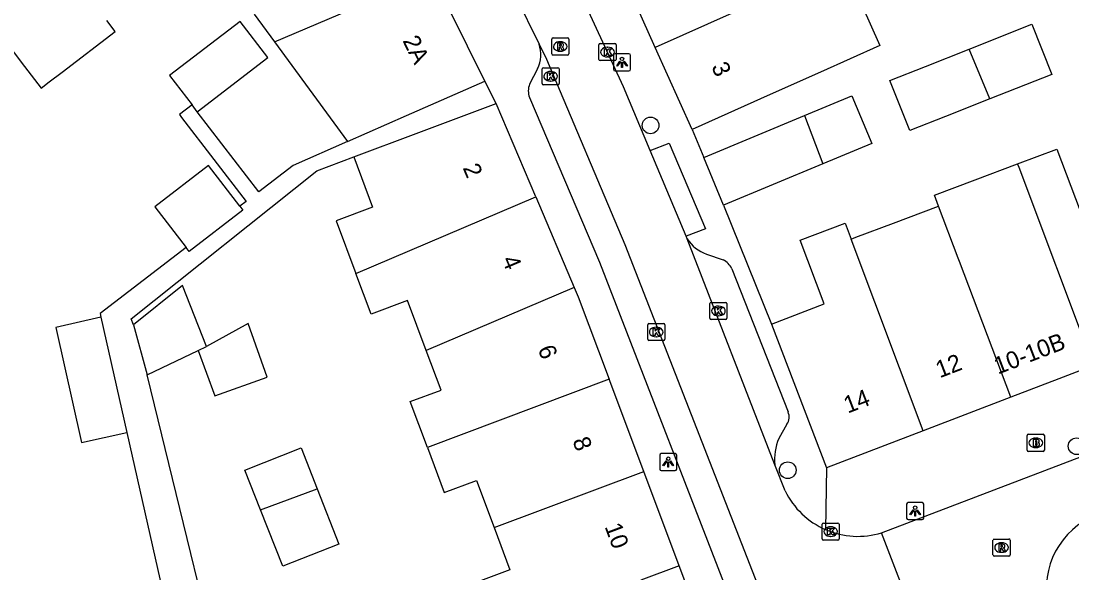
# Model space of a CAD drawing. Extents: x 159377 to 159983, y 382996 to 383595.
# Drawn here: x 159487.5 to 159549, y 383423.3 to 383455.6 of the extents above; entities that cross this region are included whole.
import ezdxf

# ---------------------------------------------------------------- set-up
doc = ezdxf.new("R2010")
doc.units = 0
for name, color, linetype in [('IMGEO_Boom', 7, 'Continuous'), ('IMGEO_Brandkraan', 7, 'Continuous'), ('IMGEO_Kolk', 7, 'Continuous'), ('IMGEO_Lichtpunt', 7, 'Continuous'), ('IMGEO_Muur', 7, 'Continuous'), ('IMGEO_Pand', 7, 'Continuous'), ('IMGEO_Pand_nummerreeks', 7, 'Continuous'), ('IMGEO_Rijbaan_lokaal_open', 7, 'Continuous'), ('IMGEO_Rioolput', 7, 'Continuous'), ('IMGEO_Voetpad_open', 7, 'Continuous')]:
    doc.layers.add(name, color=color, linetype=linetype)

msp = doc.modelspace()

# ---------------------------------------------------------------- linework, layer by layer
at = {"layer": 'IMGEO_Boom'}
for centre in [(159524.349, 383449.488), (159549.255, 383430.722), (159532.364, 383429.319)]:
    msp.add_circle(centre, 0.489, dxfattribs=at)
at = {"layer": 'IMGEO_Brandkraan'}
for p, q in [((159546.365, 383430.494), (159546.365, 383431.346)), ((159546.44, 383431.42), (159547.292, 383431.42)), ((159547.366, 383431.346), (159547.366, 383430.494)), ((159546.853, 383431.2), (159546.878, 383431.2)), ((159547.292, 383430.42), (159546.44, 383430.42)), ((159546.876, 383430.64), (159546.851, 383430.64))]:
    msp.add_line(p, q, dxfattribs=at)
for points in [[(159546.365, 383430.494), (159546.365, 383431.346)], [(159546.44, 383431.42), (159547.292, 383431.42)], [(159547.366, 383431.346), (159547.366, 383430.494)], [(159546.713, 383431.12), (159546.713, 383430.72), (159546.926, 383430.72)], [(159546.944, 383431.12), (159546.713, 383431.12)], [(159546.892, 383431.039), (159546.838, 383431.039), (159546.838, 383430.963)], [(159546.838, 383430.963), (159546.891, 383430.963)], [(159546.9, 383430.887), (159546.838, 383430.887), (159546.838, 383430.806)], [(159546.838, 383430.806), (159546.9, 383430.806)], [(159547.292, 383430.42), (159546.44, 383430.42)]]:
    msp.add_lwpolyline(points, dxfattribs=at)
for centre, radius, start, end in [((159546.442, 383431.344), 0.0765, 91.55205, 178.44795), ((159546.442, 383431.344), 0.0765, 91.55205, 178.44795), ((159547.29, 383431.344), 0.0765, 1.55205, 88.44795), ((159547.29, 383431.344), 0.0765, 1.55205, 88.44795), ((159546.893, 383431.001), 0.0379, 267.82845, 90.93552), ((159546.901, 383430.846), 0.0404, 269.87594, 90.50774), ((159546.932, 383430.971), 0.251, 268.66757, 293.53466), ((159546.948, 383430.975), 0.145, 59.4692, 91.53667), ((159546.973, 383431.022), 0.0922, 285.51372, 58.15012), ((159546.978, 383430.83), 0.105, 301.31148, 78.98903), ((159546.442, 383430.496), 0.0765, 181.55205, 268.44795), ((159546.442, 383430.496), 0.0765, 181.55205, 268.44795), ((159547.29, 383430.496), 0.0765, 271.55205, 358.44795), ((159547.29, 383430.496), 0.0765, 271.55205, 358.44795)]:
    msp.add_arc(centre, radius, start, end, dxfattribs=at)
for centre, major_axis, ratio, start_param, end_param in [((159546.852, 383430.92), (-0.387, 0.002), 0.722429, 4.712389, 7.853982), ((159546.877, 383430.92), (-0.39, 0.002), 0.717154, 1.570796, 4.712389)]:
    msp.add_ellipse(centre, major_axis=major_axis, ratio=ratio, start_param=start_param, end_param=end_param, dxfattribs=at)
at = {"layer": 'IMGEO_Kolk'}
for p, q in [((159521.33, 383453.348), (159521.33, 383454.2)), ((159521.405, 383454.274), (159522.257, 383454.274)), ((159521.818, 383454.054), (159521.843, 383454.054)), ((159522.331, 383454.2), (159522.331, 383453.348)), ((159521.841, 383453.494), (159521.816, 383453.494)), ((159518.081, 383452.86), (159518.933, 383452.86)), ((159522.257, 383453.274), (159521.405, 383453.274)), ((159518.006, 383451.934), (159518.006, 383452.786)), ((159518.494, 383452.64), (159518.519, 383452.64)), ((159519.007, 383452.786), (159519.007, 383451.934)), ((159518.933, 383451.86), (159518.081, 383451.86)), ((159518.517, 383452.08), (159518.492, 383452.08)), ((159527.812, 383438.208), (159527.812, 383439.06)), ((159527.887, 383439.134), (159528.739, 383439.134)), ((159528.3, 383438.914), (159528.325, 383438.914)), ((159528.813, 383439.06), (159528.813, 383438.208)), ((159528.739, 383438.134), (159527.887, 383438.134)), ((159528.323, 383438.354), (159528.298, 383438.354)), ((159524.181, 383436.975), (159524.181, 383437.827)), ((159524.256, 383437.901), (159525.108, 383437.901)), ((159524.669, 383437.681), (159524.694, 383437.681)), ((159525.182, 383437.827), (159525.182, 383436.975)), ((159525.108, 383436.901), (159524.256, 383436.901)), ((159524.692, 383437.121), (159524.667, 383437.121)), ((159534.375, 383425.304), (159534.375, 383426.156)), ((159534.45, 383426.23), (159535.302, 383426.23)), ((159534.863, 383426.01), (159534.888, 383426.01)), ((159535.376, 383426.156), (159535.376, 383425.304)), ((159535.302, 383425.23), (159534.45, 383425.23)), ((159534.886, 383425.45), (159534.861, 383425.45))]:
    msp.add_line(p, q, dxfattribs=at)
for points in [[(159521.33, 383453.348), (159521.33, 383454.2)], [(159521.405, 383454.274), (159522.257, 383454.274)], [(159522.331, 383454.2), (159522.331, 383453.348)], [(159521.651, 383453.974), (159521.774, 383453.974), (159521.774, 383453.823), (159521.904, 383453.974), (159522.068, 383453.974), (159521.922, 383453.823), (159522.075, 383453.574), (159521.923, 383453.574), (159521.838, 383453.738), (159521.774, 383453.671), (159521.774, 383453.574), (159521.651, 383453.574), (159521.651, 383453.974)], [(159518.081, 383452.86), (159518.933, 383452.86)], [(159522.257, 383453.274), (159521.405, 383453.274)], [(159518.006, 383451.934), (159518.006, 383452.786)], [(159518.327, 383452.56), (159518.45, 383452.56), (159518.45, 383452.409), (159518.58, 383452.56), (159518.744, 383452.56), (159518.598, 383452.409), (159518.751, 383452.16), (159518.599, 383452.16), (159518.514, 383452.324), (159518.45, 383452.257), (159518.45, 383452.16), (159518.327, 383452.16), (159518.327, 383452.56)], [(159519.007, 383452.786), (159519.007, 383451.934)], [(159518.933, 383451.86), (159518.081, 383451.86)], [(159527.812, 383438.208), (159527.812, 383439.06)], [(159527.887, 383439.134), (159528.739, 383439.134)], [(159528.133, 383438.834), (159528.256, 383438.834), (159528.256, 383438.683), (159528.386, 383438.834), (159528.55, 383438.834), (159528.404, 383438.683), (159528.557, 383438.434), (159528.405, 383438.434), (159528.32, 383438.598), (159528.256, 383438.531), (159528.256, 383438.434), (159528.133, 383438.434), (159528.133, 383438.834)], [(159528.813, 383439.06), (159528.813, 383438.208)], [(159528.739, 383438.134), (159527.887, 383438.134)], [(159524.181, 383436.975), (159524.181, 383437.827)], [(159524.256, 383437.901), (159525.108, 383437.901)], [(159524.502, 383437.601), (159524.625, 383437.601), (159524.625, 383437.45), (159524.755, 383437.601), (159524.919, 383437.601), (159524.773, 383437.45), (159524.926, 383437.201), (159524.774, 383437.201), (159524.689, 383437.365), (159524.625, 383437.298), (159524.625, 383437.201), (159524.502, 383437.201), (159524.502, 383437.601)], [(159525.182, 383437.827), (159525.182, 383436.975)], [(159525.108, 383436.901), (159524.256, 383436.901)], [(159534.375, 383425.304), (159534.375, 383426.156)], [(159534.45, 383426.23), (159535.302, 383426.23)], [(159534.696, 383425.93), (159534.819, 383425.93), (159534.819, 383425.779), (159534.949, 383425.93), (159535.113, 383425.93), (159534.967, 383425.779), (159535.12, 383425.53), (159534.968, 383425.53), (159534.883, 383425.694), (159534.819, 383425.627), (159534.819, 383425.53), (159534.696, 383425.53), (159534.696, 383425.93)], [(159535.376, 383426.156), (159535.376, 383425.304)], [(159535.302, 383425.23), (159534.45, 383425.23)]]:
    msp.add_lwpolyline(points, dxfattribs=at)
for centre, start, end in [((159521.407, 383454.198), 91.55205, 178.44795), ((159521.407, 383454.198), 91.55205, 178.44795), ((159522.255, 383454.198), 1.55205, 88.44795), ((159522.255, 383454.198), 1.55205, 88.44795), ((159518.083, 383452.784), 91.55205, 178.44795), ((159518.083, 383452.784), 91.55205, 178.44795), ((159518.931, 383452.784), 1.55205, 88.44795), ((159518.931, 383452.784), 1.55205, 88.44795), ((159521.407, 383453.35), 181.55205, 268.44795), ((159521.407, 383453.35), 181.55205, 268.44795), ((159522.255, 383453.35), 271.55205, 358.44795), ((159522.255, 383453.35), 271.55205, 358.44795), ((159518.083, 383451.936), 181.55205, 268.44795), ((159518.083, 383451.936), 181.55205, 268.44795), ((159518.931, 383451.936), 271.55205, 358.44795), ((159518.931, 383451.936), 271.55205, 358.44795), ((159527.889, 383439.058), 91.55205, 178.44795), ((159527.889, 383439.058), 91.55205, 178.44795), ((159528.737, 383439.058), 1.55205, 88.44795), ((159528.737, 383439.058), 1.55205, 88.44795), ((159527.889, 383438.21), 181.55205, 268.44795), ((159527.889, 383438.21), 181.55205, 268.44795), ((159528.737, 383438.21), 271.55205, 358.44795), ((159528.737, 383438.21), 271.55205, 358.44795), ((159524.258, 383437.825), 91.55205, 178.44795), ((159524.258, 383437.825), 91.55205, 178.44795), ((159525.106, 383437.825), 1.55205, 88.44795), ((159525.106, 383437.825), 1.55205, 88.44795), ((159524.258, 383436.977), 181.55205, 268.44795), ((159524.258, 383436.977), 181.55205, 268.44795), ((159525.106, 383436.977), 271.55205, 358.44795), ((159525.106, 383436.977), 271.55205, 358.44795), ((159534.452, 383426.154), 91.55205, 178.44795), ((159534.452, 383426.154), 91.55205, 178.44795), ((159535.3, 383426.154), 1.55205, 88.44795), ((159535.3, 383426.154), 1.55205, 88.44795), ((159534.452, 383425.306), 181.55205, 268.44795), ((159534.452, 383425.306), 181.55205, 268.44795), ((159535.3, 383425.306), 271.55205, 358.44795), ((159535.3, 383425.306), 271.55205, 358.44795)]:
    msp.add_arc(centre, 0.0765, start, end, dxfattribs=at)
for centre, major_axis, ratio, start_param, end_param in [((159521.817, 383453.774), (-0.387, 0.002), 0.722429, 4.712389, 7.853982), ((159521.842, 383453.774), (-0.39, 0.002), 0.717154, 1.570796, 4.712389), ((159518.493, 383452.36), (-0.387, 0.002), 0.722429, 4.712389, 7.853982), ((159518.518, 383452.36), (-0.39, 0.002), 0.717154, 1.570796, 4.712389), ((159528.299, 383438.634), (-0.387, 0.002), 0.722429, 4.712389, 7.853982), ((159528.324, 383438.634), (-0.39, 0.002), 0.717154, 1.570796, 4.712389), ((159524.668, 383437.401), (-0.387, 0.002), 0.722429, 4.712389, 7.853982), ((159524.693, 383437.401), (-0.39, 0.002), 0.717154, 1.570796, 4.712389), ((159534.862, 383425.73), (-0.387, 0.002), 0.722429, 4.712389, 7.853982), ((159534.887, 383425.73), (-0.39, 0.002), 0.717154, 1.570796, 4.712389)]:
    msp.add_ellipse(centre, major_axis=major_axis, ratio=ratio, start_param=start_param, end_param=end_param, dxfattribs=at)
at = {"layer": 'IMGEO_Lichtpunt'}
for p, q in [((159522.18, 383453.577), (159522.18, 383452.77)), ((159522.18, 383453.577), (159522.18, 383452.77)), ((159523.082, 383453.672), (159522.274, 383453.672)), ((159523.082, 383453.672), (159522.274, 383453.672)), ((159523.176, 383452.77), (159523.176, 383453.577)), ((159523.176, 383452.77), (159523.176, 383453.577)), ((159522.274, 383452.676), (159523.082, 383452.676)), ((159522.274, 383452.676), (159523.082, 383452.676)), ((159524.882, 383430.195), (159524.882, 383429.388)), ((159524.882, 383430.195), (159524.882, 383429.388)), ((159525.784, 383430.29), (159524.976, 383430.29)), ((159525.784, 383430.29), (159524.976, 383430.29)), ((159525.878, 383429.388), (159525.878, 383430.195)), ((159525.878, 383429.388), (159525.878, 383430.195)), ((159524.976, 383429.294), (159525.784, 383429.294)), ((159524.976, 383429.294), (159525.784, 383429.294)), ((159539.316, 383427.33), (159539.316, 383426.523)), ((159539.316, 383427.33), (159539.316, 383426.523)), ((159540.218, 383427.425), (159539.41, 383427.425)), ((159540.218, 383427.425), (159539.41, 383427.425)), ((159540.312, 383426.523), (159540.312, 383427.33)), ((159540.312, 383426.523), (159540.312, 383427.33)), ((159539.41, 383426.429), (159540.218, 383426.429)), ((159539.41, 383426.429), (159540.218, 383426.429))]:
    msp.add_line(p, q, dxfattribs=at)
for points in [[(159522.554, 383453.241), (159522.593, 383453.213), (159522.405, 383452.951), (159522.367, 383452.978), (159522.554, 383453.241)], [(159522.656, 383453.193), (159522.703, 383453.193), (159522.703, 383452.871), (159522.656, 383452.871), (159522.656, 383453.193)], [(159522.766, 383453.213), (159522.804, 383453.24), (159522.991, 383452.978), (159522.952, 383452.95), (159522.766, 383453.213)], [(159525.256, 383429.859), (159525.295, 383429.831), (159525.107, 383429.569), (159525.069, 383429.596), (159525.256, 383429.859)], [(159525.358, 383429.811), (159525.405, 383429.811), (159525.405, 383429.489), (159525.358, 383429.489), (159525.358, 383429.811)], [(159525.468, 383429.831), (159525.506, 383429.858), (159525.693, 383429.596), (159525.654, 383429.568), (159525.468, 383429.831)], [(159539.69, 383426.994), (159539.729, 383426.966), (159539.541, 383426.704), (159539.503, 383426.731), (159539.69, 383426.994)], [(159539.792, 383426.946), (159539.839, 383426.946), (159539.839, 383426.624), (159539.792, 383426.624), (159539.792, 383426.946)], [(159539.902, 383426.966), (159539.94, 383426.993), (159540.127, 383426.731), (159540.088, 383426.703), (159539.902, 383426.966)]]:
    msp.add_lwpolyline(points, dxfattribs=at)
for centre in [(159522.679, 383453.375), (159525.381, 383429.993), (159539.815, 383427.128)]:
    msp.add_circle(centre, 0.0994, dxfattribs=at)
for centre, start, end in [((159522.274, 383453.577), 90, 180), ((159522.274, 383453.577), 90, 180), ((159523.082, 383453.577), 0, 90), ((159523.082, 383453.577), 0, 90), ((159522.274, 383452.77), 180, 270), ((159522.274, 383452.77), 180, 270), ((159523.082, 383452.77), 270, 0), ((159523.082, 383452.77), 270, 360), ((159524.976, 383430.195), 90, 180), ((159524.976, 383430.195), 90, 180), ((159525.784, 383430.195), 0, 90), ((159525.784, 383430.195), 0, 90), ((159524.976, 383429.388), 180, 270), ((159524.976, 383429.388), 180, 270), ((159525.784, 383429.388), 270, 0), ((159525.784, 383429.388), 270, 360), ((159539.41, 383427.33), 90, 180), ((159539.41, 383427.33), 90, 180), ((159540.218, 383427.33), 0, 90), ((159540.218, 383427.33), 0, 90), ((159539.41, 383426.523), 180, 270), ((159539.41, 383426.523), 180, 270), ((159540.218, 383426.523), 270, 0), ((159540.218, 383426.523), 270, 360)]:
    msp.add_arc(centre, 0.0946, start, end, dxfattribs=at)
at = {"layer": 'IMGEO_Muur'}
msp.add_lwpolyline([(159528.616, 383444.818), (159531.413, 383437.858)], dxfattribs=at)
at = {"layer": 'IMGEO_Pand'}
for points in [[(159481.987, 383460.213), (159487.219, 383453.635), (159487.559, 383453.189), (159488.719, 383451.668), (159489.19, 383452.028), (159489.948, 383452.606), (159493.061, 383454.981), (159492.574, 383455.621)], [(159524.622, 383454.046), (159522.471, 383458.851)], [(159535.593, 383458.954), (159524.622, 383454.046)], [(159535.593, 383458.954), (159536.687, 383456.511), (159537.743, 383454.152), (159534.287, 383452.605), (159531.336, 383451.285), (159526.772, 383449.242)], [(159505.845, 383458.058), (159501.187, 383455.992), (159502.363, 383454.381)], [(159514.663, 383452.079), (159511.597, 383458.277)], [(159502.363, 383454.381), (159506.74, 383456.228)], [(159497.85, 383450.283), (159501.976, 383453.45), (159500.353, 383455.565), (159496.227, 383452.398), (159497.545, 383450.681)], [(159542.961, 383453.945), (159546.631, 383455.401), (159547.793, 383452.472), (159544.188, 383451.042)], [(159502.363, 383454.381), (159506.627, 383448.542)], [(159526.772, 383449.242), (159524.622, 383454.046)], [(159544.188, 383451.042), (159541.584, 383450.009), (159539.504, 383449.184), (159538.342, 383452.113), (159540.422, 383452.938), (159542.961, 383453.945)], [(159544.188, 383451.042), (159542.961, 383453.945)], [(159506.627, 383448.542), (159510.087, 383450.065), (159514.663, 383452.079)], [(159533.344, 383450.059), (159536.121, 383451.218), (159537.283, 383448.437), (159534.408, 383447.237)], [(159497.85, 383450.283), (159497.545, 383450.681)], [(159507.002, 383447.644), (159510.643, 383449.007), (159515.325, 383450.76)], [(159517.64, 383445.309), (159515.325, 383450.76)], [(159527.455, 383447.6), (159533.344, 383450.059)], [(159533.344, 383450.059), (159534.408, 383447.237)], [(159545.797, 383447.237), (159548.093, 383448.101), (159549.451, 383444.49), (159554.621, 383446.434), (159555.226, 383444.826), (159556.954, 383440.236)], [(159507.002, 383447.644), (159508.102, 383444.708), (159505.966, 383443.908), (159507.119, 383440.828)], [(159528.616, 383444.818), (159527.455, 383447.6)], [(159500.345, 383444.762), (159498.514, 383447.145), (159495.371, 383444.73), (159497.201, 383442.347)], [(159534.408, 383447.237), (159528.616, 383444.818)], [(159541.184, 383444.762), (159540.94, 383445.409), (159543.313, 383446.302), (159545.797, 383447.237)], [(159550.242, 383435.449), (159545.888, 383447.022), (159545.797, 383447.237)], [(159507.119, 383440.828), (159517.64, 383445.309)], [(159517.64, 383445.309), (159519.89, 383440.01)], [(159500.345, 383444.762), (159500.522, 383444.531), (159497.379, 383442.116), (159497.201, 383442.347)], [(159536.067, 383442.836), (159536.343, 383442.94), (159538.543, 383443.768), (159541.184, 383444.762)], [(159545.399, 383433.589), (159542.415, 383441.518), (159542.328, 383441.73), (159541.184, 383444.762)], [(159531.413, 383437.858), (159534.493, 383439.046), (159533.088, 383442.782), (159535.715, 383443.771), (159536.067, 383442.836)], [(159540.285, 383431.624), (159536.067, 383442.836)], [(159511.232, 383436.329), (159510.141, 383439.242), (159508.011, 383438.445), (159507.119, 383440.828)], [(159498.387, 383436.548), (159496.996, 383440.115), (159494.115, 383437.817)], [(159519.89, 383440.01), (159511.232, 383436.329)], [(159519.89, 383440.01), (159520.124, 383439.458), (159521.93, 383434.635)], [(159492.223, 383438.27), (159489.576, 383437.674), (159491.093, 383430.933), (159493.74, 383431.529)], [(159492.223, 383438.27), (159493.74, 383431.529)], [(159494.115, 383437.817), (159494.922, 383434.901)], [(159497.912, 383436.322), (159498.876, 383433.67), (159501.944, 383434.766), (159500.825, 383437.898), (159498.387, 383436.548)], [(159531.413, 383437.858), (159534.64, 383429.456)], [(159494.922, 383434.901), (159497.912, 383436.322)], [(159497.912, 383436.322), (159498.387, 383436.548)], [(159511.301, 383430.649), (159510.297, 383433.33), (159512.102, 383434.006), (159511.232, 383436.329)], [(159550.242, 383435.449), (159548.218, 383434.672), (159545.399, 383433.589)], [(159521.93, 383434.635), (159511.301, 383430.649)], [(159523.946, 383429.25), (159521.93, 383434.635)], [(159545.399, 383433.589), (159540.285, 383431.624)], [(159540.285, 383431.624), (159534.64, 383429.456)], [(159501.551, 383426.993), (159500.63, 383429.33), (159503.918, 383430.626), (159504.861, 383428.234)], [(159511.301, 383430.649), (159512.29, 383428.007), (159514.179, 383428.714), (159515.205, 383425.973)], [(159515.205, 383425.973), (159523.946, 383429.25)], [(159526.015, 383423.724), (159523.946, 383429.25)], [(159504.861, 383428.234), (159506.135, 383425.001), (159502.846, 383423.705), (159501.551, 383426.993)], [(159501.551, 383426.993), (159504.861, 383428.234)], [(159515.205, 383425.973), (159516.131, 383423.499), (159514.243, 383422.792), (159515.358, 383419.812)], [(159526.015, 383423.724), (159523.776, 383422.886)]]:
    msp.add_lwpolyline(points, dxfattribs=at)
at = {"layer": 'IMGEO_Rijbaan_lokaal_open'}
for points in [[(159524.331, 383448.016), (159522.767, 383451.739), (159519.986, 383457.784)], [(159516.451, 383457.066), (159517.828, 383454.245)], [(159517.828, 383454.245), (159518.267, 383453.359), (159522.834, 383442.514), (159532.286, 383418.286)], [(159526.421, 383443.01), (159524.331, 383448.016)], [(159526.492, 383442.856), (159526.421, 383443.01)], [(159531.617, 383429.639), (159526.492, 383442.856)], [(159537.852, 383425.657), (159549.947, 383430.275)], [(159532.212, 383428.113), (159531.617, 383429.639)], [(159539.935, 383420.241), (159537.852, 383425.657)]]:
    msp.add_lwpolyline(points, dxfattribs=at)
for centre, radius, start, end in [((159536.47, 383430.186), 4.736, 205.95797, 246.46401), ((159552.113, 383422.395), 4.637, 116.6432, 197.04508), ((159536.469, 383430.182), 4.732, 246.46331, 286.99671)]:
    msp.add_arc(centre, radius, start, end, dxfattribs=at)
at = {"layer": 'IMGEO_Rioolput'}
for p, q in [((159518.571, 383453.677), (159518.571, 383454.529)), ((159518.646, 383454.603), (159519.498, 383454.603)), ((159519.059, 383454.383), (159519.084, 383454.383)), ((159519.572, 383454.529), (159519.572, 383453.677)), ((159519.498, 383453.603), (159518.646, 383453.603)), ((159519.082, 383453.823), (159519.057, 383453.823)), ((159544.363, 383424.369), (159544.363, 383425.221)), ((159544.438, 383425.295), (159545.29, 383425.295)), ((159545.364, 383425.221), (159545.364, 383424.369)), ((159544.851, 383425.075), (159544.876, 383425.075)), ((159545.29, 383424.295), (159544.438, 383424.295)), ((159544.874, 383424.515), (159544.849, 383424.515))]:
    msp.add_line(p, q, dxfattribs=at)
for points in [[(159518.571, 383453.677), (159518.571, 383454.529)], [(159518.646, 383454.603), (159519.498, 383454.603)], [(159519.16, 383454.301), (159518.908, 383454.303), (159518.908, 383453.903)], [(159518.908, 383453.903), (159519.032, 383453.903), (159519.032, 383454.065), (159519.043, 383454.065)], [(159519.086, 383454.222), (159519.032, 383454.222), (159519.032, 383454.141)], [(159519.032, 383454.141), (159519.084, 383454.141)], [(159519.572, 383454.529), (159519.572, 383453.677)], [(159519.498, 383453.603), (159518.646, 383453.603)], [(159519.09, 383454.036), (159519.161, 383453.903), (159519.301, 383453.903), (159519.236, 383454.029)], [(159544.363, 383424.369), (159544.363, 383425.221)], [(159544.438, 383425.295), (159545.29, 383425.295)], [(159545.364, 383425.221), (159545.364, 383424.369)], [(159544.952, 383424.993), (159544.7, 383424.995), (159544.7, 383424.595)], [(159544.7, 383424.595), (159544.824, 383424.595), (159544.824, 383424.757), (159544.835, 383424.757)], [(159544.878, 383424.914), (159544.824, 383424.914), (159544.824, 383424.833)], [(159544.824, 383424.833), (159544.876, 383424.833)], [(159544.882, 383424.728), (159544.953, 383424.595), (159545.093, 383424.595), (159545.028, 383424.721)], [(159545.29, 383424.295), (159544.438, 383424.295)]]:
    msp.add_lwpolyline(points, dxfattribs=at)
for centre, radius, start, end in [((159518.648, 383454.527), 0.0765, 91.55205, 178.44795), ((159518.648, 383454.527), 0.0765, 91.55205, 178.44795), ((159519.042, 383454.012), 0.0533, 26.02933, 88.69889), ((159519.068, 383454.33), 0.19, 274.7715, 282.96867), ((159519.092, 383454.126), 0.0964, 77.00612, 93.18647), ((159519.106, 383454.183), 0.0378, 276.66336, 79.67722), ((159519.159, 383454.191), 0.109, 350.36119, 89.41601), ((159519.157, 383454.191), 0.112, 277.58423, 350.98172), ((159519.141, 383453.976), 0.108, 29.51342, 73.79051), ((159519.496, 383454.527), 0.0765, 1.55205, 88.44795), ((159519.496, 383454.527), 0.0765, 1.55205, 88.44795), ((159518.648, 383453.679), 0.0765, 181.55205, 268.44795), ((159518.648, 383453.679), 0.0765, 181.55205, 268.44795), ((159519.496, 383453.679), 0.0765, 271.55205, 358.44795), ((159519.496, 383453.679), 0.0765, 271.55205, 358.44795), ((159544.44, 383425.219), 0.0765, 91.55205, 178.44795), ((159544.44, 383425.219), 0.0765, 91.55205, 178.44795), ((159545.288, 383425.219), 0.0765, 1.55205, 88.44795), ((159545.288, 383425.219), 0.0765, 1.55205, 88.44795), ((159544.834, 383424.704), 0.0533, 26.02933, 88.69889), ((159544.86, 383425.022), 0.19, 274.7715, 282.96867), ((159544.884, 383424.818), 0.0964, 77.00612, 93.18647), ((159544.898, 383424.875), 0.0378, 276.66336, 79.67722), ((159544.951, 383424.883), 0.109, 350.36119, 89.41601), ((159544.949, 383424.883), 0.112, 277.58423, 350.98172), ((159544.933, 383424.668), 0.108, 29.51342, 73.79051), ((159544.44, 383424.371), 0.0765, 181.55205, 268.44795), ((159544.44, 383424.371), 0.0765, 181.55205, 268.44795), ((159545.288, 383424.371), 0.0765, 271.55205, 358.44795), ((159545.288, 383424.371), 0.0765, 271.55205, 358.44795)]:
    msp.add_arc(centre, radius, start, end, dxfattribs=at)
for centre, major_axis, ratio, start_param, end_param in [((159519.058, 383454.103), (-0.387, 0.002), 0.722429, 4.712389, 7.853982), ((159519.083, 383454.103), (-0.39, 0.002), 0.717154, 1.570796, 4.712389), ((159544.85, 383424.795), (-0.387, 0.002), 0.722429, 4.712389, 7.853982), ((159544.875, 383424.795), (-0.39, 0.002), 0.717154, 1.570796, 4.712389)]:
    msp.add_ellipse(centre, major_axis=major_axis, ratio=ratio, start_param=start_param, end_param=end_param, dxfattribs=at)
at = {"layer": 'IMGEO_Voetpad_open'}
for points in [[(159517.738, 383452.803), (159517.275, 383451.896)], [(159515.325, 383450.76), (159514.663, 383452.079)], [(159517.271, 383451.128), (159521.357, 383441.485), (159529.485, 383420.516)], [(159497.545, 383450.681), (159496.81, 383450.117), (159496.934, 383449.955), (159500.709, 383445.041), (159500.345, 383444.762)], [(159506.627, 383448.542), (159503.467, 383447.151), (159501.444, 383445.599), (159497.85, 383450.283)], [(159526.772, 383449.242), (159527.455, 383447.6)], [(159524.331, 383448.016), (159525.442, 383448.447), (159527.568, 383443.436), (159526.421, 383443.01)], [(159494.115, 383437.817), (159493.992, 383438.167), (159504.833, 383446.832), (159507.002, 383447.644)], [(159528.616, 383444.818), (159531.413, 383437.858)], [(159497.201, 383442.347), (159492.175, 383438.485), (159492.223, 383438.27)], [(159527.618, 383441.962), (159528.584, 383441.622)], [(159529.097, 383441.104), (159532.382, 383432.728)], [(159500.432, 383412.312), (159494.922, 383434.901)], [(159532.314, 383432.011), (159531.847, 383431.175)], [(159493.74, 383431.529), (159498.973, 383408.274), (159491.798, 383406.62), (159491.841, 383406.434), (159492.49, 383403.616), (159494.033, 383396.924), (159495.235, 383397.201), (159493.317, 383405.521), (159501.931, 383407.733)], [(159534.64, 383429.456), (159534.579, 383425.844)], [(159528.9, 383416.051), (159526.015, 383423.724)]]:
    msp.add_lwpolyline(points, dxfattribs=at)
for centre, radius, start, end in [((159516.195, 383453.623), 1.747, 332.00877, 20.84846), ((159518.261, 383451.507), 1.06, 158.46282, 200.94035), ((159528.284, 383443.957), 2.103, 211.56726, 251.53634), ((159528.108, 383440.638), 1.093, 25.23914, 64.20513), ((159531.775, 383432.424), 0.679, 322.53014, 26.63445), ((159534.602, 383429.977), 3.004, 156.50249, 186.46517)]:
    msp.add_arc(centre, radius, start, end, dxfattribs=at)

# ---------------------------------------------------------------- texts
at = {"layer": 'IMGEO_Pand_nummerreeks'}
for s, rotation, p in [('2A', 296.32147, (159509.834, 383454.444)), ('3', 294.1106, (159527.884, 383452.925)), ('2', 293.01058, (159513.355, 383447.007)), ('4', 292.99732, (159515.638, 383441.632)), ('10-10B', 20.9989, (159544.658, 383434.912)), ('6', 290.79282, (159517.745, 383436.416)), ('12', 21.01036, (159541.249, 383434.694)), ('14', 21.01036, (159535.872, 383432.628)), ('8', 290.52456, (159519.771, 383431.047)), ('10', 290.5265, (159521.652, 383426.022))]:
    msp.add_text(s, height=1, rotation=rotation, dxfattribs=at).set_placement(p)

doc.saveas('drawing.dxf')
